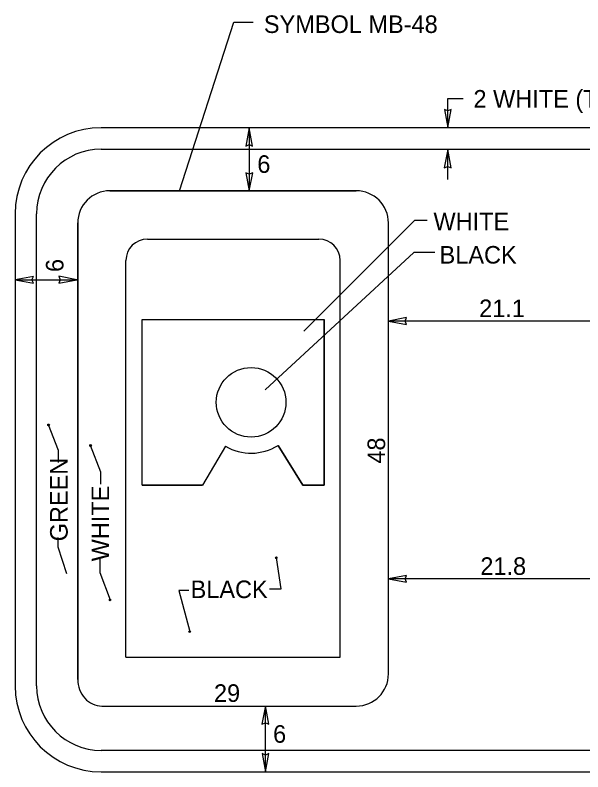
# Model space of a CAD drawing. Extents: x 319706 to 320346, y 1621790 to 1622121.
# Drawn here: x 319726.9 to 319772.1, y 1621851.1 to 1621911.4 of the extents above; entities that cross this region are included whole.
import ezdxf

# ---------------------------------------------------------------- set-up
doc = ezdxf.new("R2010")
doc.units = 0
for name, color, linetype in [('1', 7, 'Continuous'), ('52', 7, 'Continuous'), ('SignPanel', 7, 'Continuous')]:
    doc.layers.add(name, color=color, linetype=linetype)

msp = doc.modelspace()

# ---------------------------------------------------------------- linework, layer by layer
at = {"layer": '1'}
for p, q in [((319739.979, 1621897.385), (319744.299, 1621910.821)), ((319744.299, 1621910.821), (319745.847, 1621910.821)), ((319761.325, 1621902.422), (319761.325, 1621904.737)), ((319761.325, 1621904.737), (319762.556, 1621904.737)), ((319761.325, 1621898.276), (319761.325, 1621900.672)), ((319758.691, 1621895.012), (319749.865, 1621886.213)), ((319759.682, 1621895.012), (319758.691, 1621895.012)), ((319758.628, 1621892.483), (319746.806, 1621881.525)), ((319760.302, 1621892.483), (319758.628, 1621892.483)), ((319730.356, 1621876.692), (319729.55, 1621878.743)), ((319733.702, 1621874.983), (319732.895, 1621877.102)), ((319730.356, 1621875.734), (319730.356, 1621876.692)), ((319733.702, 1621874.026), (319733.702, 1621874.983)), ((319730.294, 1621869.774), (319730.294, 1621869.037)), ((319730.294, 1621869.037), (319730.975, 1621866.916)), ((319733.639, 1621868.078), (319733.639, 1621866.985)), ((319748.06, 1621865.694), (319747.688, 1621868.155)), ((319733.639, 1621866.985), (319734.445, 1621864.798)), ((319740.727, 1621865.556), (319739.922, 1621865.556)), ((319739.922, 1621865.556), (319740.79, 1621862.275)), ((319747.13, 1621865.694), (319748.06, 1621865.694))]:
    msp.add_line(p, q, dxfattribs=at)
for centre in [(319729.55, 1621878.741), (319732.896, 1621877.1), (319747.688, 1621868.153), (319734.444, 1621864.796), (319740.789, 1621862.275)]:
    msp.add_ellipse(centre, major_axis=(0, 0.0707), ratio=0.906668, dxfattribs=at)
at = {"layer": '52'}
for p, q in [((319761.325, 1621903.762), (319761.055, 1621903.872)), ((319761.055, 1621903.872), (319761.325, 1621902.422)), ((319761.325, 1621902.422), (319761.605, 1621903.872)), ((319761.605, 1621903.872), (319761.325, 1621903.762)), ((319745.528, 1621902.405), (319745.248, 1621900.955)), ((319745.798, 1621900.955), (319745.528, 1621902.405)), ((319745.248, 1621900.955), (319745.528, 1621901.065)), ((319745.528, 1621901.065), (319745.798, 1621900.955)), ((319761.325, 1621900.672), (319761.045, 1621899.222)), ((319761.595, 1621899.222), (319761.325, 1621900.672)), ((319761.045, 1621899.222), (319761.325, 1621899.332)), ((319761.325, 1621899.332), (319761.595, 1621899.222)), ((319745.528, 1621898.712), (319745.258, 1621898.822)), ((319745.258, 1621898.822), (319745.528, 1621897.372)), ((319745.528, 1621897.372), (319745.808, 1621898.822)), ((319745.808, 1621898.822), (319745.528, 1621898.712)), ((319728.343, 1621890.569), (319726.893, 1621890.299)), ((319726.893, 1621890.299), (319728.343, 1621890.019)), ((319728.233, 1621890.299), (319728.343, 1621890.569)), ((319728.343, 1621890.019), (319728.233, 1621890.299)), ((319731.81, 1621890.299), (319730.36, 1621890.579)), ((319730.36, 1621890.579), (319730.47, 1621890.299)), ((319730.47, 1621890.299), (319730.36, 1621890.029)), ((319730.36, 1621890.029), (319731.81, 1621890.299)), ((319758.055, 1621887.285), (319756.605, 1621887.015)), ((319757.945, 1621887.015), (319758.055, 1621887.285)), ((319756.605, 1621887.015), (319758.055, 1621886.735)), ((319758.055, 1621886.735), (319757.945, 1621887.015)), ((319758.055, 1621866.754), (319756.605, 1621866.484)), ((319757.945, 1621866.484), (319758.055, 1621866.754)), ((319756.605, 1621866.484), (319758.055, 1621866.204)), ((319758.055, 1621866.204), (319757.945, 1621866.484)), ((319746.811, 1621856.351), (319746.531, 1621854.901)), ((319747.081, 1621854.901), (319746.811, 1621856.351)), ((319746.531, 1621854.901), (319746.811, 1621855.011)), ((319746.811, 1621855.011), (319747.081, 1621854.901)), ((319746.811, 1621852.445), (319746.541, 1621852.555)), ((319746.541, 1621852.555), (319746.811, 1621851.105)), ((319746.811, 1621851.105), (319747.091, 1621852.555)), ((319747.091, 1621852.555), (319746.811, 1621852.445))]:
    msp.add_line(p, q, dxfattribs=at)
at = {"layer": 'SignPanel'}
for p, q in [((319843.174, 1621902.405), (319733.733, 1621902.405)), ((319745.528, 1621902.405), (319745.528, 1621897.372)), ((319733.733, 1621900.695), (319843.174, 1621900.695)), ((319734.431, 1621897.382), (319754.048, 1621897.382)), ((319754.048, 1621897.382), (319734.431, 1621897.382)), ((319726.893, 1621895.565), (319726.893, 1621857.945)), ((319728.603, 1621857.945), (319728.603, 1621895.565)), ((319731.871, 1621858.465), (319731.871, 1621894.826)), ((319731.871, 1621894.826), (319731.871, 1621858.465)), ((319756.605, 1621858.907), (319756.605, 1621894.826)), ((319756.605, 1621858.907), (319756.605, 1621894.826)), ((319737.415, 1621893.546), (319737.415, 1621893.544)), ((319737.415, 1621893.544), (319751.062, 1621893.544)), ((319735.709, 1621860.228), (319735.709, 1621891.838)), ((319752.768, 1621860.228), (319752.768, 1621891.838)), ((319726.893, 1621890.299), (319731.81, 1621890.299)), ((319736.99, 1621873.928), (319736.99, 1621887.148)), ((319736.99, 1621887.148), (319751.488, 1621887.148)), ((319736.99, 1621873.928), (319736.99, 1621887.148)), ((319736.99, 1621887.148), (319751.488, 1621887.148)), ((319751.488, 1621873.94), (319751.488, 1621887.148)), ((319751.488, 1621887.148), (319751.488, 1621873.94)), ((319775.034, 1621887.015), (319756.605, 1621887.015)), ((319743.631, 1621877.04), (319741.814, 1621873.928)), ((319743.631, 1621877.04), (319741.814, 1621873.928)), ((319747.815, 1621877.098), (319749.783, 1621873.94)), ((319749.783, 1621873.94), (319747.815, 1621877.098)), ((319736.99, 1621873.928), (319741.814, 1621873.928)), ((319741.814, 1621873.928), (319736.99, 1621873.928)), ((319749.783, 1621873.94), (319751.488, 1621873.94)), ((319751.488, 1621873.94), (319749.783, 1621873.94)), ((319775.465, 1621866.484), (319756.605, 1621866.484)), ((319735.709, 1621860.228), (319752.768, 1621860.228)), ((319733.79, 1621856.349), (319733.79, 1621856.347)), ((319733.79, 1621856.347), (319754.048, 1621856.347)), ((319733.79, 1621856.347), (319754.048, 1621856.347)), ((319746.811, 1621851.105), (319746.811, 1621856.351)), ((319843.174, 1621852.815), (319733.75, 1621852.815)), ((319733.75, 1621851.105), (319843.174, 1621851.105))]:
    msp.add_line(p, q, dxfattribs=at)
msp.add_circle((319745.674, 1621880.54), 2.772, dxfattribs=at)
for centre, radius, start, end in [((319733.733, 1621895.565), 6.84, 90, 180), ((319733.733, 1621895.565), 5.13, 90, 180), ((319734.43, 1621894.826), 2.559, 90, 180), ((319734.43, 1621894.826), 2.559, 90, 180), ((319754.047, 1621894.826), 2.559, 0, 90), ((319754.047, 1621894.826), 2.559, 0, 90), ((319737.415, 1621891.841), 1.706, 90, 180), ((319751.062, 1621891.841), 1.706, 0, 90), ((319745.674, 1621880.54), 4.051, 239.72059, 301.90487), ((319745.674, 1621880.54), 4.051, 239.72059, 301.90487), ((319754.047, 1621858.907), 2.559, 270, 360), ((319754.047, 1621858.907), 2.559, 270, 360), ((319733.733, 1621857.945), 6.84, 180, 270), ((319733.733, 1621857.945), 5.13, 180, 270)]:
    msp.add_arc(centre, radius, start, end, dxfattribs=at)
msp.add_ellipse((319733.79, 1621858.466), major_axis=(0, 2.117), ratio=0.906668, start_param=1.570796, end_param=3.141593, dxfattribs=at)
msp.add_ellipse((319733.79, 1621858.466), major_axis=(0, 2.117), ratio=0.906668, start_param=1.570796, end_param=3.141593, dxfattribs=at)

# ---------------------------------------------------------------- texts
at = {"layer": '1'}
for s, p in [('SYMBOL MB-48', (319746.691, 1621909.958)), ('2 WHITE (TYP)', (319763.371, 1621904.012)), ('WHITE', (319760.189, 1621894.25)), ('BLACK', (319760.674, 1621891.589)), ('21.1', (319763.826, 1621887.326)), ('21.8', (319763.919, 1621866.794)), ('BLACK', (319740.857, 1621864.945)), ('29', (319742.718, 1621856.679))]:
    msp.add_text(s, height=1.4, dxfattribs=at).set_placement(p)
for s, p in [('48', (319756.34, 1621875.655)), ('GREEN', (319731.073, 1621869.466)), ('WHITE', (319734.373, 1621867.872))]:
    msp.add_text(s, height=1.4, rotation=90, dxfattribs=at).set_placement(p)
at = {"layer": 'SignPanel'}
for p in [(319746.167, 1621898.816), (319747.422, 1621853.423)]:
    msp.add_text('6', height=1.4, dxfattribs=at).set_placement(p)
msp.add_text('6', height=1.4, rotation=90, dxfattribs=at).set_placement((319730.741, 1621890.918))

doc.saveas('drawing.dxf')
